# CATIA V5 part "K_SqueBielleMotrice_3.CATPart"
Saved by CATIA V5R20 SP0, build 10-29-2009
Part number: Squelette_bielle_motrice_3
Publications: "Plan_bielle_motrice_02", "Droite.1", "Droite.2"
Bounding box of the stored display mesh (mm): x -180 to -90, y -40 to 0, z 50 to 50
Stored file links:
  G:\Khaled_CFAO_2011\ST2M\ST2M_GR2\jcoetard\Khaled\CAD_CATIA\K_SqueBielleMotrice_3.CATPart
  G:\Khaled_CFAO_2011\ST2M\ST2M_GR2\jcoetard\Khaled\CAD_CATIA\K_Squelette.CATProduct
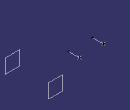
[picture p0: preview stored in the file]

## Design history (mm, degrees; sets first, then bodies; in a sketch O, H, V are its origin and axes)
Set1
  Plane1 "Plan_Ref": linked copy from another document
  Point1: linked copy from another document
  Point2: linked copy from another document
Set2 "Set géométrique"
  Plane2 "Plan_bielle_motrice_02": type Offset, RefPlane Plane1, Offset -162.303
  Line1: type Normal, RefPoint Point1, RefSkin Plane2, Start 0, End 40
  Line2: type Normal, RefPoint Point2, RefSkin Plane2, Start 0, End 40
Body1 (main body)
